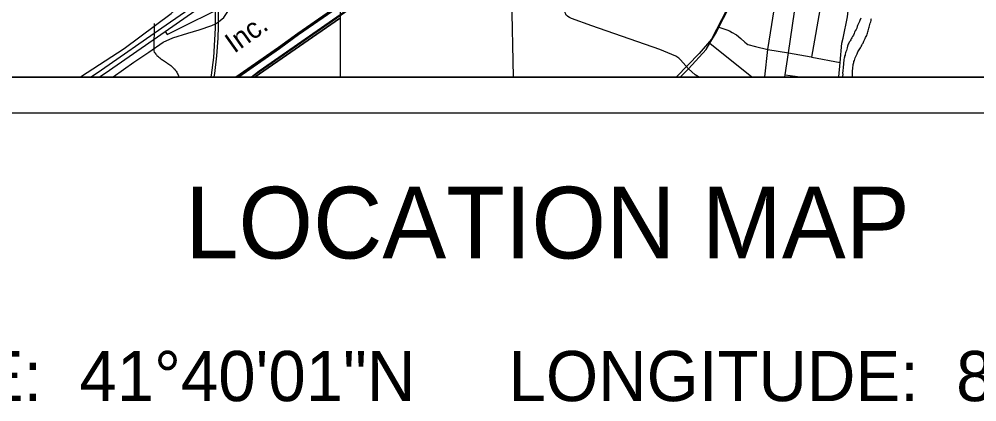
# Model space of a CAD drawing. Extents: x 0 to 34, y 0 to 22.
# Drawn here: x 3.964 to 6.635, y 13.194 to 14.261 of the extents above; entities that cross this region are included whole.
import ezdxf

# ---------------------------------------------------------------- set-up
doc = ezdxf.new("R2010")
doc.units = 0
for name, color, linetype in [('GM_X_City_Street', 7, 'Continuous'), ('GM_X_Corporation', 7, 'Continuous'), ('GM_X_County_Road', 7, 'Continuous'), ('GM_X_Interchange_Ramps', 7, 'Continuous'), ('GM_X_Major_River', 7, 'Continuous'), ('GM_X_Minor_River', 7, 'Continuous'), ('GM_X_Rail_Line', 7, 'Continuous'), ('GM_X_Rail_Line_Text', 7, 'Continuous'), ('GM_X_State_Route', 7, 'Continuous'), ('GM_X_US_Route', 7, 'Continuous'), ('SH_Data', 7, 'Continuous'), ('SH_Text', 7, 'Continuous')]:
    doc.layers.add(name, color=color, linetype=linetype)

msp = doc.modelspace()

# ---------------------------------------------------------------- linework, layer by layer
at = {"layer": 'GM_X_City_Street'}
for p, q in [((5.3428, 14.1001), (5.3329, 14.5328)), ((6.1747, 14.1558), (6.2008, 14.3036)), ((5.89, 14.1941), (6.0073, 14.1001)), ((6.1008, 14.1062), (6.1425, 14.1001))]:
    msp.add_line(p, q, dxfattribs=at)
for points in [[(6.0434, 14.1001), (6.052, 14.1771), (6.0773, 14.3345), (6.0794, 14.3479), (6.0931, 14.417), (6.1045, 14.4534), (6.1242, 14.4879)], [(5.8305, 14.1228), (5.8085, 14.1484), (5.8035, 14.1528), (5.7953, 14.1578), (5.7512, 14.1766), (5.561, 14.2427), (5.5047, 14.2631), (5.5022, 14.2643), (5.4986, 14.2661), (5.4943, 14.269), (5.4921, 14.2705), (5.4897, 14.273), (5.4887, 14.2752), (5.4872, 14.2786), (5.4855, 14.2835), (5.4852, 14.2874), (5.4834, 14.32), (5.4815, 14.3751)], [(6.0996, 14.1001), (6.1008, 14.1062), (6.1097, 14.1671), (6.1319, 14.3208)], [(5.9154, 14.2389), (5.938, 14.2312), (5.9453, 14.2284), (5.953, 14.2245), (5.9625, 14.2189), (5.9649, 14.2173), (5.9765, 14.207), (5.9877, 14.1972), (5.9929, 14.1934), (5.9966, 14.1911), (6.0176, 14.1851), (6.052, 14.1771)], [(6.052, 14.1771), (6.1097, 14.1671), (6.1733, 14.1561), (6.1747, 14.1558), (6.254, 14.1407)], [(5.8583, 14.1001), (5.8492, 14.1065), (5.8305, 14.1228)]]:
    msp.add_lwpolyline(points, dxfattribs=at)
at = {"layer": 'GM_X_Corporation'}
for points in [[(2.1001, 14.1001), (8.9001, 14.1001), (8.9001, 20.7375)], [(2.1001, 14.1001), (8.9001, 14.1001), (8.9001, 20.7375)], [(3.6337, 14.1001), (4.6221, 14.1001), (4.8577, 14.2637)], [(4.8577, 14.2637), (4.6221, 14.1001), (8.0819, 14.1001)]]:
    msp.add_lwpolyline(points, dxfattribs=at)
at = {"layer": 'GM_X_County_Road'}
for p, q in [((4.8603, 14.2081), (4.8604, 14.2584)), ((4.8601, 14.1001), (4.8603, 14.2081))]:
    msp.add_line(p, q, dxfattribs=at)
for points in [[(4.8604, 14.2584), (4.8605, 14.2825), (4.8566, 14.54), (4.8568, 14.5656), (4.8564, 14.5822), (4.8558, 14.6109), (4.8548, 14.7442)], [(4.1354, 14.1001), (4.2572, 14.1794), (4.3877, 14.2773), (4.4061, 14.2939), (4.417, 14.33), (4.413, 14.5179), (4.5077, 14.5184), (4.5161, 14.5185), (4.5398, 14.5198), (4.5528, 14.5189), (4.5635, 14.5172), (4.5738, 14.515), (4.6017, 14.5066), (4.646, 14.4933), (4.6591, 14.4903), (4.6712, 14.4893), (4.6842, 14.4906), (4.6923, 14.4928), (4.6994, 14.4962), (4.7148, 14.507), (4.7595, 14.5404), (4.8057, 14.5751), (4.8558, 14.6109)], [(4.3253, 14.1694), (4.366, 14.1975), (4.3927, 14.2091), (4.4344, 14.2221), (4.4664, 14.2318), (4.5013, 14.2436), (4.5113, 14.2488), (4.52, 14.2541), (4.5347, 14.2657), (4.5494, 14.2881), (4.5637, 14.3142), (4.5718, 14.3265), (4.5788, 14.3366), (4.5907, 14.3506), (4.6174, 14.3732), (4.6257, 14.3795)], [(4.2265, 14.1001), (4.2841, 14.141), (4.3117, 14.16), (4.3253, 14.1694)]]:
    msp.add_lwpolyline(points, dxfattribs=at)
at = {"layer": 'GM_X_Interchange_Ramps'}
msp.add_line((4.4216, 14.2406), (4.5113, 14.2851), dxfattribs=at)
msp.add_lwpolyline([(4.371, 14.2268), (4.3767, 14.2184), (4.4216, 14.2406)], dxfattribs=at)
at = {"layer": 'GM_X_Major_River'}
for points in [[(6.3114, 14.2638), (6.3088, 14.2581), (6.3073, 14.2547), (6.3059, 14.2508), (6.304, 14.247), (6.3025, 14.244), (6.3014, 14.2409), (6.2999, 14.2367), (6.2981, 14.2321), (6.2959, 14.2287), (6.294, 14.2252), (6.2925, 14.2214), (6.2907, 14.2172), (6.2881, 14.2134), (6.2862, 14.2096), (6.2843, 14.2069), (6.2832, 14.2038), (6.2818, 14.2008), (6.2803, 14.1989), (6.2791, 14.197), (6.278, 14.1943), (6.2765, 14.1912), (6.2754, 14.1889), (6.2747, 14.1863), (6.2732, 14.1813), (6.2721, 14.1775), (6.2711, 14.1737), (6.27, 14.1702), (6.2688, 14.1676), (6.2681, 14.1641), (6.2674, 14.1611), (6.2663, 14.158), (6.2656, 14.155), (6.2648, 14.1523), (6.2641, 14.1485), (6.2638, 14.1451), (6.2635, 14.1409), (6.2631, 14.1363), (6.2621, 14.1272), (6.2617, 14.1238), (6.2614, 14.1199), (6.2611, 14.1161), (6.2607, 14.112), (6.2608, 14.107), (6.2605, 14.1021), (6.2608, 14.1001)], [(6.2887, 14.1236), (6.2905, 14.1347), (6.2912, 14.1381), (6.2915, 14.1408), (6.2923, 14.1431), (6.2934, 14.1465), (6.2945, 14.1499), (6.296, 14.1534), (6.2974, 14.1572), (6.2993, 14.1614), (6.3008, 14.1648), (6.3022, 14.1679), (6.3034, 14.1706), (6.3052, 14.1733), (6.3067, 14.1759), (6.3082, 14.179), (6.3101, 14.1817), (6.3119, 14.1851), (6.3138, 14.1882), (6.3153, 14.1916), (6.3183, 14.1947), (6.3201, 14.2), (6.322, 14.2035), (6.3234, 14.2073), (6.3249, 14.21), (6.326, 14.2126), (6.3279, 14.2157), (6.329, 14.2191), (6.3297, 14.2222), (6.3308, 14.2256), (6.3319, 14.229), (6.3326, 14.2321), (6.3337, 14.2359), (6.3345, 14.239), (6.3352, 14.2428), (6.3367, 14.2466), (6.3378, 14.25), (6.3389, 14.2538), (6.34, 14.2573), (6.3407, 14.2611), (6.3414, 14.2637)], [(6.2892, 14.1001), (6.2886, 14.1027), (6.2881, 14.1054), (6.2881, 14.1088), (6.2881, 14.1134), (6.2884, 14.1176), (6.2887, 14.1236)]]:
    msp.add_lwpolyline(points, dxfattribs=at)
at = {"layer": 'GM_X_Minor_River'}
msp.add_lwpolyline([(4.3405, 14.2497), (4.3406, 14.2447), (4.3406, 14.2421), (4.3406, 14.2398), (4.3407, 14.2371), (4.3407, 14.2352), (4.3407, 14.2326), (4.3408, 14.2299), (4.3408, 14.228), (4.3404, 14.2257), (4.3405, 14.2231), (4.3405, 14.2204), (4.3401, 14.2181), (4.3402, 14.2158), (4.3402, 14.2136), (4.3398, 14.2105), (4.3399, 14.2075), (4.3399, 14.2048), (4.3396, 14.2021), (4.3396, 14.1991), (4.3396, 14.1968), (4.3393, 14.1941), (4.3397, 14.1881), (4.3394, 14.1843), (4.3394, 14.1808), (4.3394, 14.1782), (4.3395, 14.1759), (4.3399, 14.1732), (4.3407, 14.1698), (4.3422, 14.1676), (4.3453, 14.1642), (4.3472, 14.1615), (4.3484, 14.1596), (4.3503, 14.1585), (4.3534, 14.1555), (4.356, 14.1532), (4.3591, 14.1506), (4.3622, 14.1487), (4.3641, 14.1476), (4.3668, 14.1457), (4.369, 14.1446), (4.3717, 14.1427), (4.3748, 14.1405), (4.3767, 14.139), (4.3786, 14.1379), (4.3813, 14.1356), (4.384, 14.1341), (4.387, 14.1319), (4.3897, 14.1296), (4.3928, 14.1266), (4.3955, 14.124), (4.3978, 14.1217), (4.3993, 14.1194), (4.4016, 14.116), (4.4039, 14.1134), (4.4051, 14.1111), (4.4059, 14.1092), (4.4071, 14.1062), (4.4086, 14.1032), (4.4094, 14.1001), (4.4094, 14.1001)], dxfattribs=at)
at = {"layer": 'GM_X_Rail_Line'}
for points in [[(4.6122, 14.1001), (4.6338, 14.1175), (5.119, 14.4555), (5.3409, 14.6098), (5.7171, 14.8714), (5.73, 14.8795), (5.7451, 14.8885), (5.7594, 14.8959), (5.7746, 14.9032), (5.7915, 14.9099), (5.8045, 14.9146), (5.8192, 14.9189), (5.8364, 14.9234), (5.8527, 14.9268), (5.867, 14.929), (5.886, 14.9311), (5.9054, 14.9322), (5.9284, 14.9327), (5.9468, 14.9329), (6.0103, 14.9313)], [(6.0488, 14.5029), (5.8946, 14.2056), (5.861, 14.1656), (5.7975, 14.1001)], [(4.6128, 14.1001), (5.1203, 14.4536)], [(4.5686, 14.1001), (4.6874, 14.1829), (4.7408, 14.2226), (4.9169, 14.3454)], [(4.5727, 14.1001), (4.6887, 14.181), (4.7422, 14.2207), (4.9182, 14.3435)], [(4.5767, 14.1001), (4.6901, 14.1791), (4.7435, 14.2188), (4.9196, 14.3416)]]:
    msp.add_lwpolyline(points, dxfattribs=at)
at = {"layer": 'GM_X_State_Route'}
for points in [[(4.1651, 14.1001), (4.1933, 14.1196), (4.3619, 14.2373), (4.4252, 14.2812), (4.5102, 14.341), (4.5186, 14.3468), (4.6044, 14.406)], [(4.5113, 14.2488), (4.5113, 14.2851), (4.5103, 14.325), (4.5102, 14.341), (4.51, 14.3892)], [(4.371, 14.2268), (4.4325, 14.2699), (4.5103, 14.325), (4.5187, 14.331), (4.526, 14.336)], [(4.52, 14.2541), (4.52, 14.2894), (4.5187, 14.331), (4.5186, 14.3366)], [(6.2617, 14.2085), (6.2747, 14.2683), (6.2761, 14.2847), (6.2772, 14.2987), (6.2778, 14.3048)], [(4.4996, 14.1001), (4.5006, 14.1053), (4.5069, 14.1544), (4.51, 14.204), (4.5115, 14.2362), (4.5113, 14.2488)], [(4.5076, 14.1001), (4.5093, 14.1095), (4.5157, 14.1587), (4.5187, 14.2082), (4.5203, 14.2405), (4.52, 14.2541)], [(4.1882, 14.1001), (4.204, 14.1111), (4.371, 14.2268)], [(6.2505, 14.1001), (6.254, 14.1407), (6.2587, 14.1942), (6.2617, 14.2085)]]:
    msp.add_lwpolyline(points, dxfattribs=at)
at = {"layer": 'GM_X_US_Route'}
msp.add_lwpolyline([(5.8083, 14.1001), (5.8305, 14.1228), (5.8798, 14.1768), (5.89, 14.1941), (5.9085, 14.2253), (5.9154, 14.2389), (5.9283, 14.2645), (5.9765, 14.3598), (6.0452, 14.4955), (6.1074, 14.6184)], dxfattribs=at)
at = {"layer": 'SH_Data'}
for p, q in [((2.1, 14.1), (8.9, 14.1)), ((2, 14), (9, 14))]:
    msp.add_line(p, q, dxfattribs=at)

# ---------------------------------------------------------------- texts
at = {"layer": 'GM_X_Rail_Line_Text'}
msp.add_text('Inc.', height=0.05663, rotation=35.3705, dxfattribs=at).set_placement((4.5638, 14.1645))
at = {"layer": 'SH_Text'}
for s, height, p in [('LOCATION MAP', 0.2, (4.4269, 13.5938)), ('LATITUDE:  41°40\'01"N     LONGITUDE:  81°25\'32"W', 0.14, (3.071, 13.1959))]:
    msp.add_text(s, height=height, dxfattribs=at).set_placement(p)

doc.saveas('drawing.dxf')
